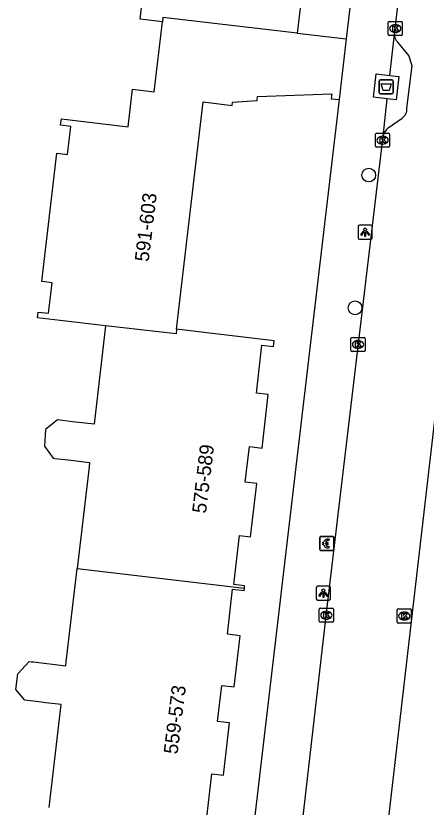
# Model space of a CAD drawing. Extents: x 160861 to 161308, y 384024 to 384878.
# Drawn here: x 161227.7 to 161256.9, y 384587.8 to 384644.1 of the extents above; entities that cross this region are included whole.
import ezdxf

# ---------------------------------------------------------------- set-up
doc = ezdxf.new("R2010")
doc.units = 0
for name, color, linetype in [('IMGEO_Afval_apart_plaats', 7, 'Continuous'), ('IMGEO_Betaalautomaat', 7, 'Continuous'), ('IMGEO_Boom', 7, 'Continuous'), ('IMGEO_Kolk', 7, 'Continuous'), ('IMGEO_Lichtpunt', 7, 'Continuous'), ('IMGEO_Pand', 7, 'Continuous'), ('IMGEO_Pand_nummerreeks', 7, 'Continuous'), ('IMGEO_Rijbaan_lokaal_open', 7, 'Continuous'), ('IMGEO_Voetpad_gesloten', 7, 'Continuous'), ('IMGEO_Voetpad_open', 7, 'Continuous')]:
    doc.layers.add(name, color=color, linetype=linetype)

msp = doc.modelspace()

# ---------------------------------------------------------------- linework, layer by layer
at = {"layer": 'IMGEO_Afval_apart_plaats'}
for p, q in [((161253.565, 384638.63), (161253.565, 384639.43)), ((161253.565, 384639.43), (161253.565, 384638.63)), ((161253.665, 384639.53), (161254.455, 384639.53)), ((161254.455, 384639.53), (161253.665, 384639.53)), ((161254.555, 384639.43), (161254.555, 384638.63)), ((161254.555, 384638.63), (161254.555, 384639.43)), ((161254.455, 384638.53), (161253.665, 384638.53)), ((161253.665, 384638.53), (161254.455, 384638.53))]:
    msp.add_line(p, q, dxfattribs=at)
msp.add_lwpolyline([(161253.708, 384639.244), (161254.412, 384639.244), (161254.263, 384638.774), (161253.857, 384638.774), (161253.708, 384639.244)], dxfattribs=at)
for centre, start, end in [((161253.665, 384639.43), 90, 180), ((161253.665, 384639.43), 90, 180), ((161254.455, 384639.43), 0, 90), ((161254.455, 384639.43), 360, 90), ((161253.665, 384638.63), 180, 270), ((161253.665, 384638.63), 180, 270), ((161254.455, 384638.63), 270, 0), ((161254.455, 384638.63), 270, 0)]:
    msp.add_arc(centre, 0.1, start, end, dxfattribs=at)
at = {"layer": 'IMGEO_Betaalautomaat'}
for p, q in [((161249.348, 384606.138), (161249.348, 384606.979)), ((161249.348, 384606.979), (161249.348, 384606.138)), ((161249.423, 384607.062), (161250.264, 384607.062)), ((161250.264, 384607.062), (161249.423, 384607.062)), ((161249.631, 384606.526), (161249.631, 384606.594)), ((161249.752, 384606.594), (161249.752, 384606.526)), ((161250.01, 384606.867), (161249.993, 384606.767)), ((161250.347, 384606.988), (161250.347, 384606.147)), ((161250.347, 384606.147), (161250.347, 384606.988)), ((161250.273, 384606.063), (161249.432, 384606.063)), ((161249.432, 384606.063), (161250.273, 384606.063)), ((161249.997, 384606.361), (161250.019, 384606.274))]:
    msp.add_line(p, q, dxfattribs=at)
for points in [[(161249.631, 384606.594), (161249.562, 384606.594), (161249.562, 384606.663), (161249.641, 384606.663)], [(161249.636, 384606.457), (161249.562, 384606.457), (161249.562, 384606.526), (161249.631, 384606.526)], [(161249.763, 384606.663), (161249.91, 384606.663), (161249.91, 384606.594), (161249.752, 384606.594)], [(161249.752, 384606.526), (161249.91, 384606.526), (161249.91, 384606.457), (161249.766, 384606.457)]]:
    msp.add_lwpolyline(points, dxfattribs=at)
for centre, radius, start, end in [((161249.426, 384606.985), 0.0779, 92.4484, 184.2845), ((161249.426, 384606.985), 0.0779, 92.4484, 184.2845), ((161249.924, 384606.587), 0.293, 73.014, 165.0139), ((161249.93, 384606.6), 0.179, 69.3236, 159.5683), ((161250.27, 384606.985), 0.0779, 2.4484, 94.2845), ((161250.27, 384606.985), 0.0779, 2.4484, 94.2845), ((161249.426, 384606.141), 0.0779, 182.4484, 274.2845), ((161249.426, 384606.141), 0.0779, 182.4484, 274.2845), ((161249.897, 384606.512), 0.267, 191.8096, 297.0389), ((161249.93, 384606.527), 0.179, 202.7625, 291.8693), ((161250.27, 384606.141), 0.0779, 272.4484, 4.2845), ((161250.27, 384606.141), 0.0779, 272.4484, 4.2845)]:
    msp.add_arc(centre, radius, start, end, dxfattribs=at)
at = {"layer": 'IMGEO_Boom'}
for centre in [(161252.822, 384632.757), (161251.848, 384623.316)]:
    msp.add_circle(centre, 0.489, dxfattribs=at)
at = {"layer": 'IMGEO_Kolk'}
for p, q in [((161254.283, 384643.677), (161255.135, 384643.677)), ((161254.208, 384642.751), (161254.208, 384643.603)), ((161254.696, 384643.457), (161254.721, 384643.457)), ((161255.209, 384643.603), (161255.209, 384642.751)), ((161255.135, 384642.677), (161254.283, 384642.677)), ((161254.719, 384642.897), (161254.694, 384642.897)), ((161253.306, 384634.815), (161253.306, 384635.667)), ((161253.381, 384635.741), (161254.233, 384635.741)), ((161253.794, 384635.521), (161253.819, 384635.521)), ((161254.307, 384635.667), (161254.307, 384634.815)), ((161254.233, 384634.741), (161253.381, 384634.741)), ((161253.817, 384634.961), (161253.792, 384634.961)), ((161251.636, 384621.213), (161252.488, 384621.213)), ((161251.561, 384620.287), (161251.561, 384621.139)), ((161252.049, 384620.993), (161252.074, 384620.993)), ((161252.562, 384621.139), (161252.562, 384620.287)), ((161252.488, 384620.213), (161251.636, 384620.213)), ((161252.072, 384620.433), (161252.047, 384620.433)), ((161249.311, 384601.034), (161249.311, 384601.886)), ((161249.386, 384601.96), (161250.238, 384601.96)), ((161249.799, 384601.74), (161249.824, 384601.74)), ((161250.312, 384601.886), (161250.312, 384601.034)), ((161254.848, 384600.978), (161254.848, 384601.83)), ((161254.923, 384601.904), (161255.775, 384601.904)), ((161255.336, 384601.684), (161255.361, 384601.684)), ((161255.849, 384601.83), (161255.849, 384600.978)), ((161250.238, 384600.96), (161249.386, 384600.96)), ((161249.822, 384601.18), (161249.797, 384601.18)), ((161255.775, 384600.904), (161254.923, 384600.904)), ((161255.359, 384601.124), (161255.334, 384601.124))]:
    msp.add_line(p, q, dxfattribs=at)
for points in [[(161254.283, 384643.677), (161255.135, 384643.677)], [(161254.208, 384642.751), (161254.208, 384643.603)], [(161254.529, 384643.377), (161254.652, 384643.377), (161254.652, 384643.226), (161254.782, 384643.377), (161254.946, 384643.377), (161254.8, 384643.226), (161254.953, 384642.977), (161254.801, 384642.977), (161254.716, 384643.141), (161254.652, 384643.074), (161254.652, 384642.977), (161254.529, 384642.977), (161254.529, 384643.377)], [(161255.209, 384643.603), (161255.209, 384642.751)], [(161255.135, 384642.677), (161254.283, 384642.677)], [(161253.306, 384634.815), (161253.306, 384635.667)], [(161253.381, 384635.741), (161254.233, 384635.741)], [(161253.627, 384635.441), (161253.75, 384635.441), (161253.75, 384635.29), (161253.88, 384635.441), (161254.044, 384635.441), (161253.898, 384635.29), (161254.051, 384635.041), (161253.899, 384635.041), (161253.814, 384635.205), (161253.75, 384635.138), (161253.75, 384635.041), (161253.627, 384635.041), (161253.627, 384635.441)], [(161254.307, 384635.667), (161254.307, 384634.815)], [(161254.233, 384634.741), (161253.381, 384634.741)], [(161251.636, 384621.213), (161252.488, 384621.213)], [(161251.561, 384620.287), (161251.561, 384621.139)], [(161251.882, 384620.913), (161252.005, 384620.913), (161252.005, 384620.762), (161252.135, 384620.913), (161252.299, 384620.913), (161252.153, 384620.762), (161252.306, 384620.513), (161252.154, 384620.513), (161252.069, 384620.677), (161252.005, 384620.61), (161252.005, 384620.513), (161251.882, 384620.513), (161251.882, 384620.913)], [(161252.562, 384621.139), (161252.562, 384620.287)], [(161252.488, 384620.213), (161251.636, 384620.213)], [(161249.311, 384601.034), (161249.311, 384601.886)], [(161249.386, 384601.96), (161250.238, 384601.96)], [(161249.632, 384601.66), (161249.755, 384601.66), (161249.755, 384601.509), (161249.885, 384601.66), (161250.049, 384601.66), (161249.903, 384601.509), (161250.056, 384601.26), (161249.904, 384601.26), (161249.819, 384601.424), (161249.755, 384601.357), (161249.755, 384601.26), (161249.632, 384601.26), (161249.632, 384601.66)], [(161250.312, 384601.886), (161250.312, 384601.034)], [(161254.848, 384600.978), (161254.848, 384601.83)], [(161254.923, 384601.904), (161255.775, 384601.904)], [(161255.169, 384601.604), (161255.292, 384601.604), (161255.292, 384601.453), (161255.422, 384601.604), (161255.586, 384601.604), (161255.44, 384601.453), (161255.593, 384601.204), (161255.441, 384601.204), (161255.356, 384601.368), (161255.292, 384601.301), (161255.292, 384601.204), (161255.169, 384601.204), (161255.169, 384601.604)], [(161255.849, 384601.83), (161255.849, 384600.978)], [(161250.238, 384600.96), (161249.386, 384600.96)], [(161255.775, 384600.904), (161254.923, 384600.904)]]:
    msp.add_lwpolyline(points, dxfattribs=at)
for centre, start, end in [((161254.285, 384643.601), 91.552, 178.448), ((161254.285, 384643.601), 91.552, 178.448), ((161255.133, 384643.601), 1.552, 88.448), ((161255.133, 384643.601), 1.552, 88.448), ((161254.285, 384642.753), 181.552, 268.448), ((161254.285, 384642.753), 181.552, 268.448), ((161255.133, 384642.753), 271.552, 358.448), ((161255.133, 384642.753), 271.552, 358.448), ((161253.383, 384635.665), 91.552, 178.448), ((161253.383, 384635.665), 91.552, 178.448), ((161254.231, 384635.665), 1.552, 88.448), ((161254.231, 384635.665), 1.552, 88.448), ((161253.383, 384634.817), 181.552, 268.448), ((161253.383, 384634.817), 181.552, 268.448), ((161254.231, 384634.817), 271.552, 358.448), ((161254.231, 384634.817), 271.552, 358.448), ((161251.638, 384621.137), 91.552, 178.448), ((161251.638, 384621.137), 91.552, 178.448), ((161252.486, 384621.137), 1.552, 88.448), ((161252.486, 384621.137), 1.552, 88.448), ((161251.638, 384620.289), 181.552, 268.448), ((161251.638, 384620.289), 181.552, 268.448), ((161252.486, 384620.289), 271.552, 358.448), ((161252.486, 384620.289), 271.552, 358.448), ((161249.388, 384601.884), 91.552, 178.448), ((161249.388, 384601.884), 91.552, 178.448), ((161250.236, 384601.884), 1.552, 88.448), ((161250.236, 384601.884), 1.552, 88.448), ((161254.925, 384601.828), 91.552, 178.448), ((161254.925, 384601.828), 91.552, 178.448), ((161255.773, 384601.828), 1.552, 88.448), ((161255.773, 384601.828), 1.552, 88.448), ((161249.388, 384601.036), 181.552, 268.448), ((161249.388, 384601.036), 181.552, 268.448), ((161250.236, 384601.036), 271.552, 358.448), ((161250.236, 384601.036), 271.552, 358.448), ((161254.925, 384600.98), 181.552, 268.448), ((161254.925, 384600.98), 181.552, 268.448), ((161255.773, 384600.98), 271.552, 358.448), ((161255.773, 384600.98), 271.552, 358.448)]:
    msp.add_arc(centre, 0.0765, start, end, dxfattribs=at)
for centre, major_axis, ratio, start_param, end_param in [((161254.695, 384643.177), (-0.387, 0.002), 0.722429, 4.712389, 7.853982), ((161254.72, 384643.177), (-0.39, 0.002), 0.717154, 1.570796, 4.712389), ((161253.793, 384635.241), (-0.387, 0.002), 0.722429, 4.712389, 7.853982), ((161253.818, 384635.241), (-0.39, 0.002), 0.717154, 1.570796, 4.712389), ((161252.048, 384620.713), (-0.387, 0.002), 0.722429, 4.712389, 7.853982), ((161252.073, 384620.713), (-0.39, 0.002), 0.717154, 1.570796, 4.712389), ((161249.798, 384601.46), (-0.387, 0.002), 0.722429, 4.712389, 7.853982), ((161249.823, 384601.46), (-0.39, 0.002), 0.717154, 1.570796, 4.712389), ((161255.335, 384601.404), (-0.387, 0.002), 0.722429, 4.712389, 7.853982), ((161255.36, 384601.404), (-0.39, 0.002), 0.717154, 1.570796, 4.712389)]:
    msp.add_ellipse(centre, major_axis=major_axis, ratio=ratio, start_param=start_param, end_param=end_param, dxfattribs=at)
at = {"layer": 'IMGEO_Lichtpunt'}
for p, q in [((161252.072, 384629.098), (161252.072, 384628.291)), ((161252.072, 384629.098), (161252.072, 384628.291)), ((161252.974, 384629.193), (161252.166, 384629.193)), ((161252.974, 384629.193), (161252.166, 384629.193)), ((161253.068, 384628.291), (161253.068, 384629.098)), ((161253.068, 384628.291), (161253.068, 384629.098)), ((161252.166, 384628.197), (161252.974, 384628.197)), ((161252.166, 384628.197), (161252.974, 384628.197)), ((161249.098, 384603.429), (161249.098, 384602.622)), ((161249.098, 384603.429), (161249.098, 384602.622)), ((161250, 384603.524), (161249.192, 384603.524)), ((161250, 384603.524), (161249.192, 384603.524)), ((161250.094, 384602.622), (161250.094, 384603.429)), ((161250.094, 384602.622), (161250.094, 384603.429)), ((161249.192, 384602.528), (161250, 384602.528)), ((161249.192, 384602.528), (161250, 384602.528))]:
    msp.add_line(p, q, dxfattribs=at)
for points in [[(161252.446, 384628.762), (161252.485, 384628.734), (161252.297, 384628.472), (161252.259, 384628.499), (161252.446, 384628.762)], [(161252.548, 384628.714), (161252.595, 384628.714), (161252.595, 384628.392), (161252.548, 384628.392), (161252.548, 384628.714)], [(161252.658, 384628.734), (161252.696, 384628.761), (161252.883, 384628.499), (161252.844, 384628.471), (161252.658, 384628.734)], [(161249.472, 384603.093), (161249.511, 384603.065), (161249.323, 384602.803), (161249.285, 384602.83), (161249.472, 384603.093)], [(161249.574, 384603.045), (161249.621, 384603.045), (161249.621, 384602.723), (161249.574, 384602.723), (161249.574, 384603.045)], [(161249.684, 384603.065), (161249.722, 384603.092), (161249.909, 384602.83), (161249.87, 384602.802), (161249.684, 384603.065)]]:
    msp.add_lwpolyline(points, dxfattribs=at)
for centre in [(161252.571, 384628.896), (161249.597, 384603.227)]:
    msp.add_circle(centre, 0.0994, dxfattribs=at)
for centre, start, end in [((161252.166, 384629.098), 90, 180), ((161252.166, 384629.098), 90, 180), ((161252.974, 384629.098), 0, 90), ((161252.974, 384629.098), 0, 90), ((161252.166, 384628.291), 180, 270), ((161252.166, 384628.291), 180, 270), ((161252.974, 384628.291), 270, 0), ((161252.974, 384628.291), 270, 360), ((161249.192, 384603.429), 90, 180), ((161249.192, 384603.429), 90, 180), ((161250, 384603.429), 0, 90), ((161250, 384603.429), 0, 90), ((161249.192, 384602.622), 180, 270), ((161249.192, 384602.622), 180, 270), ((161250, 384602.622), 270, 0), ((161250, 384602.622), 270, 360)]:
    msp.add_arc(centre, 0.0946, start, end, dxfattribs=at)
at = {"layer": 'IMGEO_Pand'}
for points in [[(161238.156, 384643.665), (161236.57, 384643.85), (161237.35, 384650.52)], [(161248.138, 384646.226), (161247.742, 384642.842)], [(161234.126, 384622.045), (161229.28, 384622.612), (161229.327, 384623.015), (161230.073, 384622.927), (161230.328, 384625.106), (161229.589, 384625.192), (161230.655, 384634.305), (161231.406, 384634.218), (161231.64, 384636.215), (161230.925, 384636.299), (161230.978, 384636.75), (161235.715, 384636.196), (161236.026, 384638.854), (161237.572, 384638.673), (161238.156, 384643.665)], [(161247.742, 384642.842), (161238.19, 384643.959), (161238.156, 384643.665)], [(161247.742, 384642.842), (161251.223, 384642.435)], [(161251.223, 384642.435), (161250.719, 384638.124)], [(161239.167, 384621.793), (161241.057, 384637.954), (161243.111, 384637.713), (161243.138, 384637.94), (161244.891, 384638.051), (161244.925, 384638.343), (161250.196, 384638.529), (161250.156, 384638.19), (161250.719, 384638.124)], [(161234.126, 384622.045), (161233.307, 384615.04), (161231.771, 384615.22), (161230.71, 384615.344), (161229.854, 384614.658), (161229.789, 384613.483), (161230.392, 384612.623), (161230.508, 384612.609), (161230.749, 384612.581), (161231.452, 384612.499), (161232.982, 384612.32), (161232.945, 384612.002), (161232.099, 384604.776)], [(161239.167, 384621.793), (161239.128, 384621.46), (161234.126, 384622.045)], [(161243.982, 384603.385), (161244.002, 384603.557), (161243.228, 384603.648), (161243.634, 384607.121), (161244.419, 384607.029), (161244.863, 384610.826), (161244.05, 384610.921), (161244.346, 384613.452), (161245.242, 384613.347), (161245.686, 384617.145), (161244.835, 384617.245), (161245.234, 384620.653), (161246.046, 384620.558), (161246.096, 384620.983), (161241.313, 384621.542), (161239.167, 384621.793)], [(161230.112, 384587.792), (161230.968, 384595.109), (161229.882, 384595.236), (161229.369, 384595.296), (161228.377, 384595.412), (161227.742, 384596.171), (161227.889, 384597.292), (161228.7, 384598.172), (161228.862, 384598.153), (161229.008, 384598.136), (161231.291, 384597.869), (161231.325, 384598.157), (161232.099, 384604.776)], [(161232.099, 384604.776), (161243.982, 384603.385)], [(161242.051, 384586.395), (161242.071, 384586.571), (161241.263, 384586.665), (161241.674, 384590.186), (161242.493, 384590.09), (161242.928, 384593.807), (161242.074, 384593.906), (161242.375, 384596.473), (161243.27, 384596.368), (161243.695, 384600.001), (161242.776, 384600.108), (161243.151, 384603.309), (161243.962, 384603.214), (161243.982, 384603.385)]]:
    msp.add_lwpolyline(points, dxfattribs=at)
at = {"layer": 'IMGEO_Rijbaan_lokaal_open'}
for points in [[(161254.652, 384642.767), (161254.663, 384642.875), (161254.769, 384643.763), (161256.647, 384659.845)], [(161251.981, 384567.454), (161262.507, 384658.314)], [(161255.536, 384637.513), (161255.912, 384640.526), (161255.674, 384641.253), (161254.887, 384642.219)], [(161254.206, 384636.117), (161255.187, 384636.801)], [(161237.656, 384495.995), (161237.777, 384496.96), (161238.057, 384500), (161239.778, 384514.805), (161243.381, 384545.472), (161249.855, 384601.831), (161250.766, 384609.622), (161253.738, 384634.519), (161253.842, 384635.509)]]:
    msp.add_lwpolyline(points, dxfattribs=at)
for centre, radius, start, end in [((161255.359, 384642.746), 0.708, 178.3006, 228.1218), ((161254.752, 384637.456), 0.786, 303.5899, 4.1848), ((161254.923, 384635.275), 1.106, 130.401, 167.7824)]:
    msp.add_arc(centre, radius, start, end, dxfattribs=at)
at = {"layer": 'IMGEO_Voetpad_gesloten'}
for points in [[(161254.139, 384638.175), (161253.156, 384638.287), (161253.346, 384639.957), (161254.326, 384639.846)], [(161254.326, 384639.846), (161254.964, 384639.773), (161254.774, 384638.103), (161254.139, 384638.175)]]:
    msp.add_lwpolyline(points, dxfattribs=at)
at = {"layer": 'IMGEO_Voetpad_open'}
for points in [[(161253.755, 384663.908), (161251.223, 384642.435)], [(161254.326, 384639.846), (161254.652, 384642.767)], [(161250.719, 384638.124), (161247.412, 384609.996), (161242.554, 384568.674)], [(161253.842, 384635.509), (161254.139, 384638.175)]]:
    msp.add_lwpolyline(points, dxfattribs=at)

# ---------------------------------------------------------------- texts
at = {"layer": 'IMGEO_Pand_nummerreeks'}
for s, rotation, p in [('591-603', 83.0888, (161237.177, 384626.555)), ('575-589', 83.1706, (161241.255, 384608.666)), ('559-573', 82.9242, (161239.231, 384591.545))]:
    msp.add_text(s, height=1, rotation=rotation, dxfattribs=at).set_placement(p)

doc.saveas('drawing.dxf')
